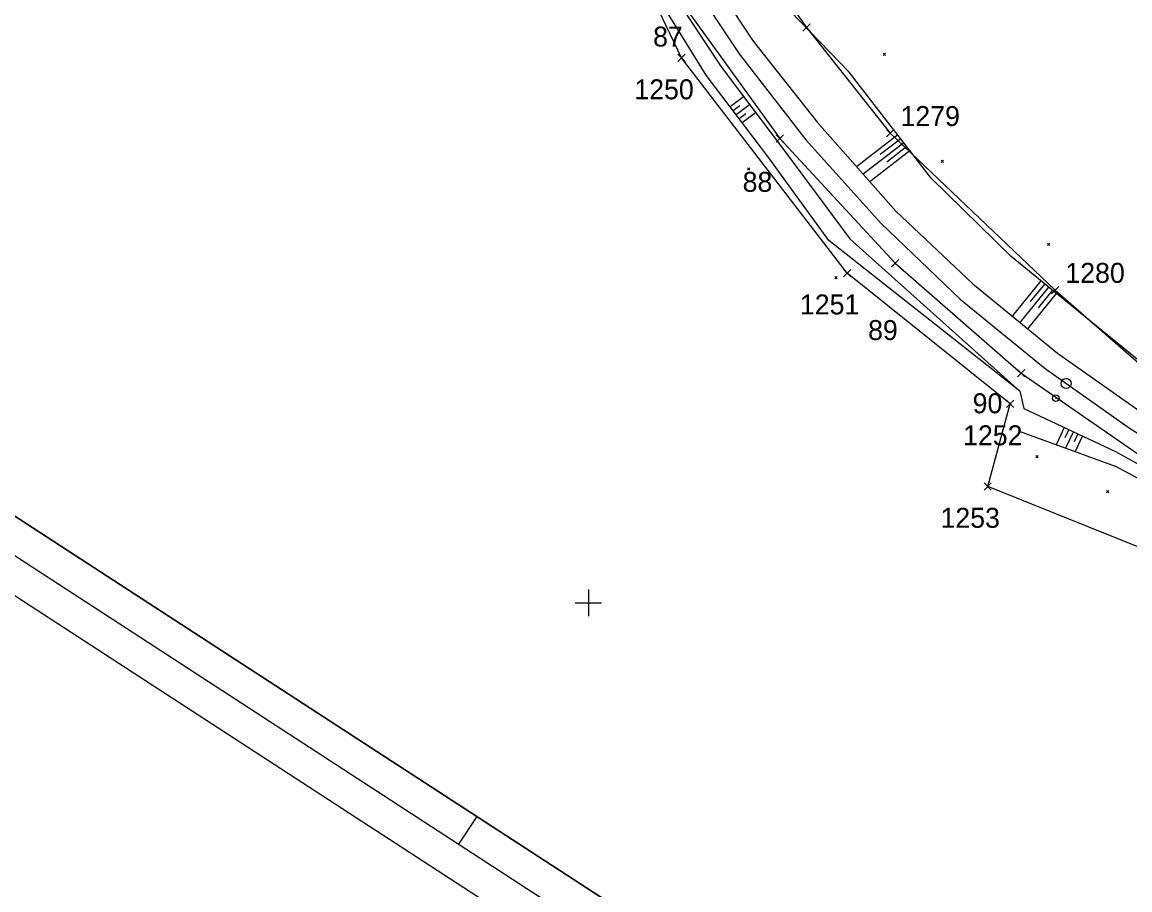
# Model space of a CAD drawing. Extents: x -866402 to -860377, y -1041908 to -1038598.
# Drawn here: x -861885.1 to -861718.6, y -1039643.2 to -1039512.7 of the extents above; entities that cross this region are included whole.
import ezdxf

# ---------------------------------------------------------------- set-up
doc = ezdxf.new("R2010")
doc.units = 0
for name, color, linetype in [('PS 01 trasa', 7, 'Continuous'), ('PS 02 trasa', 7, 'Continuous'), ('SZDC', 7, 'Continuous'), ('Vrstva 1', 7, 'Continuous'), ('Vrstva 48', 7, 'Continuous'), ('Vrstva 49', 7, 'Continuous'), ('Vrstva 5', 7, 'Continuous'), ('Vrstva 60', 7, 'Continuous'), ('Vrstva 7', 7, 'Continuous')]:
    doc.layers.add(name, color=color, linetype=linetype)

msp = doc.modelspace()

# ---------------------------------------------------------------- linework, layer by layer
at = {"layer": 'PS 01 trasa'}
msp.add_lwpolyline([(-861859.77, -1039380.3), (-861844.87, -1039399.82), (-861835.42, -1039415.87), (-861831.94, -1039421.16), (-861820.58, -1039443.39), (-861809.77, -1039465.79), (-861798.74, -1039487.92), (-861788.87, -1039504.85), (-861785.97, -1039509.83), (-861771.22, -1039530.2), (-861753.86, -1039548.94), (-861734.94, -1039565.48), (-861714.17, -1039579.85)], dxfattribs=at)
at = {"layer": 'PS 02 trasa'}
msp.add_lwpolyline([(-861859.77, -1039380.3), (-861844.87, -1039399.82), (-861835.42, -1039415.87), (-861831.94, -1039421.16), (-861820.58, -1039443.39), (-861809.77, -1039465.79), (-861798.74, -1039487.92), (-861785.97, -1039509.83), (-861771.22, -1039530.2), (-861753.86, -1039548.94), (-861734.94, -1039565.48), (-861714.17, -1039579.85)], dxfattribs=at)
at = {"layer": 'SZDC'}
for points in [[(-861669.39, -1039610.88), (-861739.98, -1039582.51), (-861736.58, -1039570.11), (-861761.11, -1039550.44), (-861785.99, -1039518.1), (-861810.72, -1039466.47), (-861837.37, -1039424.62), (-861848.52, -1039406.82), (-861855.53, -1039393.66), (-861857.34, -1039390.64), (-861896.85, -1039350.33), (-861915.3, -1039338.57), (-861931.91, -1039330.04), (-861947.75, -1039322.96), (-861987.36, -1039308.17), (-862085.83, -1039279.58), (-862090.03, -1039278.64), (-862095.47, -1039277.41), (-862098.88, -1039276.65), (-862122.58, -1039271.04), (-862135.01, -1039264.12), (-862179.78, -1039258.36), (-862197.34, -1039258.12), (-862239.36, -1039240.49)], [(-861871.45, -1039352.97), (-861839.12, -1039385.66), (-861823.12, -1039370.41), (-861814.46, -1039390.55), (-861815.33, -1039397.99), (-861816.53, -1039408.19), (-861817.32, -1039414.91), (-861813.7, -1039438.87), (-861805.31, -1039452.81), (-861794.94, -1039459.16), (-861778.03, -1039466.96), (-861788.92, -1039482.88), (-861767.19, -1039513.52), (-861754.63, -1039529.43), (-861729.85, -1039553), (-861707.85, -1039572.19)]]:
    msp.add_lwpolyline(points, dxfattribs=at)
at = {"layer": 'Vrstva 1'}
msp.add_line((-861816.78, -1039632.12), (-861819.51, -1039636.31), dxfattribs=at)
for points in [[(-862350.36, -1039297.02), (-861294.1, -1039983.97), (-861132.18, -1039735), (-862188.44, -1039048.05)], [(-862186.98, -1039054.97), (-861139.1, -1039736.46), (-861295.57, -1039977.05), (-862343.44, -1039295.55)], [(-862336.53, -1039294.09), (-861468.88, -1039858.37), (-861317.86, -1039626.16), (-862185.51, -1039061.88)], [(-862185.51, -1039061.88), (-861317.86, -1039626.16), (-861468.88, -1039858.37), (-862336.53, -1039294.09)]]:
    msp.add_lwpolyline(points, close=True, dxfattribs=at)
msp.add_lwpolyline([(-861806.57, -1039466.19), (-861802.77, -1039473.87), (-861795.16, -1039488.58), (-861786.79, -1039503.21), (-861777.33, -1039517.47), (-861767.29, -1039530.41), (-861756.03, -1039542.96), (-861744.1, -1039554.37), (-861731.34, -1039564.81), (-861718.5, -1039573.84), (-861704.36, -1039582.33), (-861689.46, -1039590.11), (-861674.47, -1039597.17), (-861659.39, -1039604)], dxfattribs=at)
at = {"layer": 'Vrstva 48'}
for p, q in [((-861778.7, -1039525.42), (-861776.68, -1039523.89)), ((-861778.24, -1039526.02), (-861777.23, -1039525.25)), ((-861777.79, -1039526.62), (-861775.77, -1039525.09)), ((-861776.88, -1039527.81), (-861774.87, -1039526.29)), ((-861777.34, -1039527.21), (-861776.33, -1039526.45)), ((-861753.49, -1039529.65), (-861759.7, -1039534.46)), ((-861752.57, -1039530.84), (-861758.71, -1039535.59)), ((-861753.03, -1039530.25), (-861756.12, -1039532.64)), ((-861751.65, -1039532.03), (-861757.71, -1039536.72)), ((-861752.11, -1039531.43), (-861755.16, -1039533.79)), ((-861731.98, -1039551.59), (-861736.32, -1039556.9)), ((-861730.82, -1039552.54), (-861735.16, -1039557.85)), ((-861731.4, -1039552.06), (-861733.57, -1039554.72)), ((-861729.66, -1039553.49), (-861734, -1039558.81)), ((-861730.24, -1039553.01), (-861732.41, -1039555.67)), ((-861728.46, -1039573.64), (-861729.69, -1039576.24)), ((-861727.78, -1039573.96), (-861728.38, -1039575.23)), ((-861727.1, -1039574.28), (-861728.27, -1039576.76)), ((-861726.43, -1039574.6), (-861726.99, -1039575.8)), ((-861725.75, -1039574.92), (-861726.85, -1039577.27))]:
    msp.add_line(p, q, dxfattribs=at)
at = {"layer": 'Vrstva 49'}
for p, q in [((-861755.69, -1039517.37), (-861755.34, -1039517.72)), ((-861755.69, -1039517.72), (-861755.34, -1039517.37)), ((-861776.1, -1039534.63), (-861775.74, -1039534.98)), ((-861776.1, -1039534.98), (-861775.74, -1039534.63)), ((-861746.99, -1039533.48), (-861746.64, -1039533.83)), ((-861746.99, -1039533.83), (-861746.64, -1039533.48)), ((-861735.13, -1039568.2), (-861763.84, -1039545.56)), ((-861760.71, -1039545.28), (-861735.13, -1039568.2)), ((-861730.99, -1039545.94), (-861730.64, -1039546.29)), ((-861730.99, -1039546.29), (-861730.64, -1039545.94)), ((-861762.95, -1039550.94), (-861762.6, -1039551.3)), ((-861762.95, -1039551.3), (-861762.6, -1039550.94)), ((-861735.13, -1039568.2), (-861734.53, -1039570.79)), ((-861734.53, -1039570.79), (-861720.79, -1039577.25)), ((-861735.27, -1039574.2), (-861720.83, -1039579.47)), ((-861732.73, -1039577.86), (-861732.38, -1039578.21)), ((-861732.73, -1039578.21), (-861732.38, -1039577.86)), ((-861722.1, -1039583.11), (-861721.75, -1039583.46)), ((-861722.1, -1039583.46), (-861721.75, -1039583.11))]:
    msp.add_line(p, q, dxfattribs=at)
for points in [[(-861800.02, -1039472.46), (-861791.33, -1039489.79), (-861784.32, -1039501.82), (-861775.23, -1039515.56), (-861765.55, -1039527.83), (-861753.79, -1039541.16), (-861742.23, -1039552.06), (-861729.5, -1039562.5), (-861717.12, -1039571.2), (-861702.84, -1039579.73), (-861688.14, -1039587.47), (-861673.27, -1039594.57), (-861658.14, -1039601.18), (-861643.02, -1039608.06), (-861628.53, -1039614.89), (-861613.05, -1039621.77), (-861598.1, -1039629.35)], [(-861763.84, -1039545.56), (-861772.85, -1039533.13), (-861782.27, -1039520.7), (-861791.53, -1039505.77), (-861800.22, -1039488.88), (-861806.84, -1039475.16)], [(-861805.56, -1039475.19), (-861797.79, -1039490.3), (-861789.66, -1039504.86), (-861780.04, -1039519.43), (-861770.5, -1039532.08), (-861760.71, -1039545.28)], [(-861597.49, -1039628.06), (-861608.55, -1039622.04), (-861628.17, -1039611.58), (-861641.27, -1039604.73), (-861656.44, -1039598.15), (-861670.44, -1039592.92), (-861685.95, -1039585.64), (-861700.43, -1039577.6), (-861713.44, -1039566.69), (-861724.4, -1039557.79), (-861736.43, -1039547.96), (-861748.45, -1039536.17), (-861760.78, -1039520.24), (-861769.59, -1039511.11), (-861778.23, -1039498.91)], [(-861720.79, -1039577.25), (-861706.62, -1039585.07), (-861691.24, -1039593.1), (-861677.89, -1039599.5), (-861659.07, -1039612.43)], [(-861659.07, -1039612.43), (-861682.56, -1039598.92), (-861692.14, -1039594.15), (-861709.22, -1039585.7), (-861720.83, -1039579.47)]]:
    msp.add_lwpolyline(points, dxfattribs=at)
at = {"layer": 'Vrstva 5'}
for p, q in [((-861800, -1039598), (-861800, -1039602)), ((-861802, -1039600), (-861798, -1039600))]:
    msp.add_line(p, q, dxfattribs=at)
at = {"layer": 'Vrstva 60'}
for p, q in [((-861766.74, -1039513.97), (-861767.74, -1039512.97)), ((-861767.64, -1039513.97), (-861766.64, -1039512.97)), ((-861766.74, -1039513.07), (-861767.74, -1039514.07)), ((-861767.64, -1039513.07), (-861766.64, -1039514.07)), ((-861767.19, -1039513.52), (-861767.19, -1039513.52)), ((-861785.54, -1039518.55), (-861786.54, -1039517.55)), ((-861785.54, -1039517.65), (-861786.54, -1039518.65)), ((-861786.44, -1039518.55), (-861785.44, -1039517.55)), ((-861786.44, -1039517.65), (-861785.44, -1039518.65)), ((-861785.99, -1039518.1), (-861785.99, -1039518.1)), ((-861770.77, -1039530.65), (-861771.77, -1039529.65)), ((-861771.67, -1039530.65), (-861770.67, -1039529.65)), ((-861754.18, -1039529.88), (-861755.18, -1039528.88)), ((-861754.18, -1039528.98), (-861755.18, -1039529.98)), ((-861755.08, -1039529.88), (-861754.08, -1039528.88)), ((-861755.08, -1039528.98), (-861754.08, -1039529.98)), ((-861754.63, -1039529.43), (-861754.63, -1039529.43)), ((-861770.77, -1039529.75), (-861771.77, -1039530.75)), ((-861771.67, -1039529.75), (-861770.67, -1039530.75)), ((-861771.22, -1039530.2), (-861771.22, -1039530.2)), ((-861753.41, -1039549.39), (-861754.41, -1039548.39)), ((-861753.41, -1039548.49), (-861754.41, -1039549.49)), ((-861754.31, -1039549.39), (-861753.31, -1039548.39)), ((-861754.31, -1039548.49), (-861753.31, -1039549.49)), ((-861753.86, -1039548.94), (-861753.86, -1039548.94)), ((-861760.66, -1039550.89), (-861761.66, -1039549.89)), ((-861760.66, -1039549.99), (-861761.66, -1039550.99)), ((-861761.56, -1039550.89), (-861760.56, -1039549.89)), ((-861761.56, -1039549.99), (-861760.56, -1039550.99)), ((-861761.11, -1039550.44), (-861761.11, -1039550.44)), ((-861729.4, -1039553.45), (-861730.4, -1039552.45)), ((-861729.4, -1039552.55), (-861730.4, -1039553.55)), ((-861730.3, -1039553.45), (-861729.3, -1039552.45)), ((-861730.3, -1039552.55), (-861729.3, -1039553.55)), ((-861729.85, -1039553), (-861729.85, -1039553)), ((-861734.49, -1039565.93), (-861735.49, -1039564.93)), ((-861734.49, -1039565.03), (-861735.49, -1039566.03)), ((-861735.39, -1039565.93), (-861734.39, -1039564.93)), ((-861735.39, -1039565.03), (-861734.39, -1039566.03)), ((-861734.94, -1039565.48), (-861734.94, -1039565.48)), ((-861736.13, -1039570.56), (-861737.13, -1039569.56)), ((-861737.03, -1039570.56), (-861736.03, -1039569.56)), ((-861736.13, -1039569.66), (-861737.13, -1039570.66)), ((-861737.03, -1039569.66), (-861736.03, -1039570.66)), ((-861736.58, -1039570.11), (-861736.58, -1039570.11)), ((-861739.53, -1039582.96), (-861740.53, -1039581.96)), ((-861739.53, -1039582.06), (-861740.53, -1039583.06)), ((-861740.43, -1039582.96), (-861739.43, -1039581.96)), ((-861740.43, -1039582.06), (-861739.43, -1039583.06)), ((-861739.98, -1039582.51), (-861739.98, -1039582.51))]:
    msp.add_line(p, q, dxfattribs=at)
at = {"layer": 'Vrstva 7'}
msp.add_line((-861729.78, -1039569.26), (-861729.68, -1039569.26), dxfattribs=at)
for centre, radius in [((-861728.19, -1039567.03), 0.75), ((-861729.73, -1039569.26), 0.5)]:
    msp.add_circle(centre, radius, dxfattribs=at)

# ---------------------------------------------------------------- texts
at = {"layer": 'Vrstva 60'}
for s, p in [('87', (-861790.26, -1039516.39)), ('1250', (-861793.08, -1039524.32)), ('1279', (-861753.08, -1039528.34)), ('88', (-861776.81, -1039538.23)), ('1280', (-861728.3, -1039551.91)), ('1251', (-861768.2, -1039556.66)), ('89', (-861757.95, -1039560.51)), ('90', (-861742.24, -1039571.52)), ('1252', (-861743.67, -1039576.33)), ('1253', (-861747.07, -1039588.73))]:
    msp.add_text(s, height=3, dxfattribs=at).set_placement(p)

doc.saveas('drawing.dxf')
